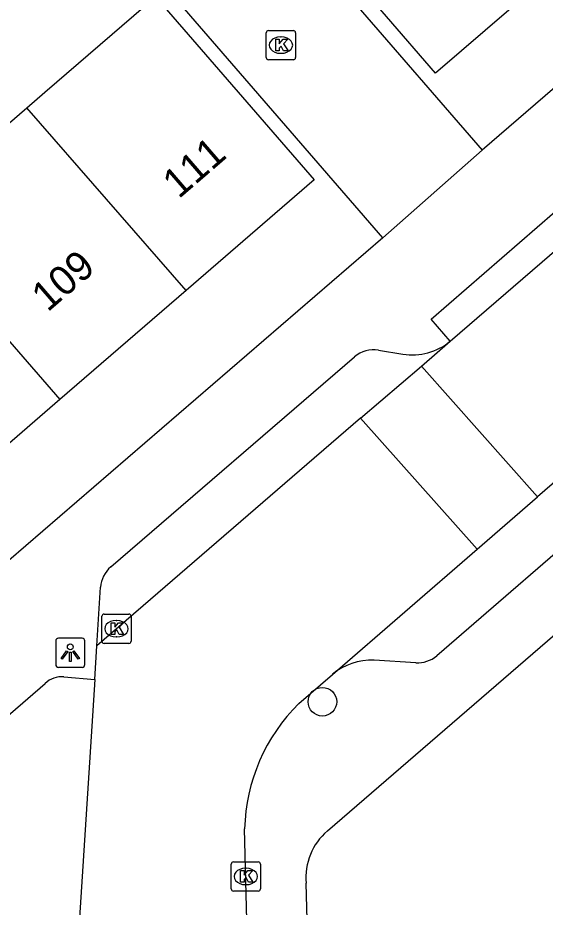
# Model space of a CAD drawing. Extents: x 160304 to 160954, y 383686 to 384161.
# Drawn here: x 160578.41 to 160596.44, y 384040.18 to 384070.59 of the extents above; entities that cross this region are included whole.
import ezdxf

# ---------------------------------------------------------------- set-up
doc = ezdxf.new("R2010")
doc.units = 0
for name, color, linetype in [('IMGEO_Boom', 7, 'Continuous'), ('IMGEO_Kolk', 7, 'Continuous'), ('IMGEO_Lichtpunt', 7, 'Continuous'), ('IMGEO_Pand', 7, 'Continuous'), ('IMGEO_Pand_nummerreeks', 7, 'Continuous'), ('IMGEO_Rijbaan_lokaal_open', 7, 'Continuous'), ('IMGEO_Voetpad_open', 7, 'Continuous')]:
    doc.layers.add(name, color=color, linetype=linetype)

msp = doc.modelspace()

# ---------------------------------------------------------------- linework, layer by layer
at = {"layer": 'IMGEO_Boom'}
msp.add_circle((160588.824, 384047.207), 0.489, dxfattribs=at)
at = {"layer": 'IMGEO_Kolk'}
for p, q in [((160586.905, 384069.225), (160586.905, 384070.077)), ((160586.98, 384070.151), (160587.832, 384070.151)), ((160587.393, 384069.931), (160587.418, 384069.931)), ((160587.906, 384070.077), (160587.906, 384069.225)), ((160587.416, 384069.371), (160587.391, 384069.371)), ((160587.832, 384069.151), (160586.98, 384069.151)), ((160581.357, 384050.203), (160582.209, 384050.203)), ((160581.282, 384049.277), (160581.282, 384050.129)), ((160581.77, 384049.983), (160581.795, 384049.983)), ((160582.283, 384050.129), (160582.283, 384049.277)), ((160581.793, 384049.423), (160581.768, 384049.423)), ((160582.209, 384049.203), (160581.357, 384049.203)), ((160585.705, 384040.809), (160585.705, 384041.661)), ((160585.78, 384041.735), (160586.632, 384041.735)), ((160586.706, 384041.661), (160586.706, 384040.809)), ((160586.193, 384041.515), (160586.218, 384041.515)), ((160586.632, 384040.735), (160585.78, 384040.735)), ((160586.216, 384040.955), (160586.191, 384040.955))]:
    msp.add_line(p, q, dxfattribs=at)
for points in [[(160586.905, 384069.225), (160586.905, 384070.077)], [(160586.98, 384070.151), (160587.832, 384070.151)], [(160587.906, 384070.077), (160587.906, 384069.225)], [(160587.226, 384069.851), (160587.349, 384069.851), (160587.349, 384069.7), (160587.479, 384069.851), (160587.643, 384069.851), (160587.497, 384069.7), (160587.65, 384069.451), (160587.498, 384069.451), (160587.413, 384069.615), (160587.349, 384069.548), (160587.349, 384069.451), (160587.226, 384069.451), (160587.226, 384069.851)], [(160587.832, 384069.151), (160586.98, 384069.151)], [(160581.357, 384050.203), (160582.209, 384050.203)], [(160581.282, 384049.277), (160581.282, 384050.129)], [(160581.603, 384049.903), (160581.726, 384049.903), (160581.726, 384049.752), (160581.856, 384049.903), (160582.02, 384049.903), (160581.874, 384049.752), (160582.027, 384049.503), (160581.875, 384049.503), (160581.79, 384049.667), (160581.726, 384049.6), (160581.726, 384049.503), (160581.603, 384049.503), (160581.603, 384049.903)], [(160582.283, 384050.129), (160582.283, 384049.277)], [(160582.209, 384049.203), (160581.357, 384049.203)], [(160585.705, 384040.809), (160585.705, 384041.661)], [(160585.78, 384041.735), (160586.632, 384041.735)], [(160586.706, 384041.661), (160586.706, 384040.809)], [(160586.026, 384041.435), (160586.149, 384041.435), (160586.149, 384041.284), (160586.279, 384041.435), (160586.443, 384041.435), (160586.297, 384041.284), (160586.45, 384041.035), (160586.298, 384041.035), (160586.213, 384041.199), (160586.149, 384041.132), (160586.149, 384041.035), (160586.026, 384041.035), (160586.026, 384041.435)], [(160586.632, 384040.735), (160585.78, 384040.735)]]:
    msp.add_lwpolyline(points, dxfattribs=at)
for centre, start, end in [((160586.982, 384070.075), 91.552, 178.448), ((160586.982, 384070.075), 91.552, 178.448), ((160587.83, 384070.075), 1.552, 88.448), ((160587.83, 384070.075), 1.552, 88.448), ((160586.982, 384069.227), 181.552, 268.448), ((160586.982, 384069.227), 181.552, 268.448), ((160587.83, 384069.227), 271.552, 358.448), ((160587.83, 384069.227), 271.552, 358.448), ((160581.359, 384050.127), 91.552, 178.448), ((160581.359, 384050.127), 91.552, 178.448), ((160582.207, 384050.127), 1.552, 88.448), ((160582.207, 384050.127), 1.552, 88.448), ((160581.359, 384049.279), 181.552, 268.448), ((160581.359, 384049.279), 181.552, 268.448), ((160582.207, 384049.279), 271.552, 358.448), ((160582.207, 384049.279), 271.552, 358.448), ((160585.782, 384041.659), 91.552, 178.448), ((160585.782, 384041.659), 91.552, 178.448), ((160586.63, 384041.659), 1.552, 88.448), ((160586.63, 384041.659), 1.552, 88.448), ((160585.782, 384040.811), 181.552, 268.448), ((160585.782, 384040.811), 181.552, 268.448), ((160586.63, 384040.811), 271.552, 358.448), ((160586.63, 384040.811), 271.552, 358.448)]:
    msp.add_arc(centre, 0.0765, start, end, dxfattribs=at)
for centre, major_axis, ratio, start_param, end_param in [((160587.392, 384069.651), (-0.387, 0.002), 0.722429, 4.712389, 7.853982), ((160587.417, 384069.651), (-0.39, 0.002), 0.717154, 1.570796, 4.712389), ((160581.769, 384049.703), (-0.387, 0.002), 0.722429, 4.712389, 7.853982), ((160581.794, 384049.703), (-0.39, 0.002), 0.717154, 1.570796, 4.712389), ((160586.192, 384041.235), (-0.387, 0.002), 0.722429, 4.712389, 7.853982), ((160586.217, 384041.235), (-0.39, 0.002), 0.717154, 1.570796, 4.712389)]:
    msp.add_ellipse(centre, major_axis=major_axis, ratio=ratio, start_param=start_param, end_param=end_param, dxfattribs=at)
at = {"layer": 'IMGEO_Lichtpunt'}
for p, q in [((160579.705, 384049.285), (160579.705, 384048.478)), ((160579.705, 384049.285), (160579.705, 384048.478)), ((160580.607, 384049.38), (160579.799, 384049.38)), ((160580.607, 384049.38), (160579.799, 384049.38)), ((160580.701, 384048.478), (160580.701, 384049.285)), ((160580.701, 384048.478), (160580.701, 384049.285)), ((160579.799, 384048.384), (160580.607, 384048.384)), ((160579.799, 384048.384), (160580.607, 384048.384))]:
    msp.add_line(p, q, dxfattribs=at)
for points in [[(160580.079, 384048.949), (160580.118, 384048.921), (160579.93, 384048.659), (160579.892, 384048.686), (160580.079, 384048.949)], [(160580.291, 384048.921), (160580.329, 384048.948), (160580.516, 384048.686), (160580.477, 384048.658), (160580.291, 384048.921)], [(160580.181, 384048.901), (160580.228, 384048.901), (160580.228, 384048.579), (160580.181, 384048.579), (160580.181, 384048.901)]]:
    msp.add_lwpolyline(points, dxfattribs=at)
msp.add_circle((160580.204, 384049.083), 0.0994, dxfattribs=at)
for centre, start, end in [((160579.799, 384049.285), 90, 180), ((160579.799, 384049.285), 90, 180), ((160580.607, 384049.285), 0, 90), ((160580.607, 384049.285), 0, 90), ((160579.799, 384048.478), 180, 270), ((160579.799, 384048.478), 180, 270), ((160580.607, 384048.478), 270, 0), ((160580.607, 384048.478), 270, 360)]:
    msp.add_arc(centre, 0.0946, start, end, dxfattribs=at)
at = {"layer": 'IMGEO_Pand'}
for points in [[(160596.974, 384072.386), (160592.694, 384068.69), (160587.665, 384074.513), (160585.913, 384076.542), (160590.193, 384080.238), (160591.945, 384078.209)], [(160578.719, 384067.513), (160579.338, 384068.048), (160583.122, 384071.316), (160588.539, 384065.044), (160584.165, 384061.267)], [(160574.41, 384063.793), (160578.719, 384067.513)], [(160584.165, 384061.267), (160578.719, 384067.513)], [(160574.41, 384063.793), (160579.845, 384057.535)], [(160584.165, 384061.267), (160579.845, 384057.535)], [(160579.845, 384057.535), (160575.545, 384053.821)]]:
    msp.add_lwpolyline(points, dxfattribs=at)
at = {"layer": 'IMGEO_Rijbaan_lokaal_open'}
for points in [[(160578.615, 384084.142), (160585.508, 384076.191), (160594.287, 384066.063)], [(160590.891, 384063.065), (160578.802, 384077.039), (160575.999, 384077.117)], [(160611.687, 384067.609), (160596.18, 384054.208)], [(160594.287, 384066.063), (160590.891, 384063.065)], [(160593.19, 384059.531), (160597.248, 384063.027), (160597.427, 384063.191)], [(160592.207, 384058.683), (160593.19, 384059.531)], [(160590.131, 384056.895), (160592.207, 384058.683)], [(160596.18, 384054.208), (160592.207, 384058.683)], [(160590.131, 384056.895), (160581.111, 384049.123)], [(160594.111, 384052.42), (160590.131, 384056.895)], [(160594.111, 384052.42), (160596.18, 384054.208)], [(160589.163, 384048.144), (160594.111, 384052.42)], [(160581.037, 384047.97), (160581.111, 384049.123)], [(160588.016, 384047.153), (160589.163, 384048.144)], [(160581.037, 384047.97), (160580.353, 384037.334)], [(160586.437, 384032.15), (160586.162, 384042.862)]]:
    msp.add_lwpolyline(points, dxfattribs=at)
msp.add_arc((160592.455, 384042.689), 6.295, 134.8395, 178.4253, dxfattribs=at)
at = {"layer": 'IMGEO_Voetpad_open'}
for points in [[(160630.096, 384096.946), (160594.287, 384066.063)], [(160588.993, 384042.795), (160607.555, 384058.819), (160616.616, 384066.641), (160617.548, 384067.446)], [(160610.683, 384064.29), (160592.733, 384048.779)], [(160593.19, 384059.531), (160592.537, 384060.288), (160596.775, 384063.949), (160597.427, 384063.191)], [(160590.891, 384063.065), (160577.514, 384051.539), (160577.428, 384049.127), (160562.223, 384035.951)], [(160581.585, 384051.814), (160589.923, 384058.999)], [(160590.739, 384059.228), (160591.577, 384059.089)], [(160581.111, 384049.123), (160581.24, 384051.121)], [(160592.018, 384048.537), (160590.591, 384048.625)], [(160579.979, 384048.063), (160581.037, 384047.97)], [(160576.201, 384045.119), (160579.344, 384047.835)], [(160588.54, 384030.95), (160588.268, 384041.002)]]:
    msp.add_lwpolyline(points, dxfattribs=at)
for centre, radius, start, end in [((160591.904, 384061.059), 1.997, 260.5677, 310.0807), ((160590.577, 384058.238), 1.003, 80.6908, 130.6614), ((160582.242, 384051.055), 1.004, 130.8634, 176.2051), ((160590.513, 384046.497), 2.13, 87.8977, 129.3329), ((160592.078, 384049.537), 1.001, 266.5598, 310.8381), ((160579.936, 384047.186), 0.879, 87.17, 132.3318), ((160590.352, 384041.202), 2.094, 130.4793, 185.4888)]:
    msp.add_arc(centre, radius, start, end, dxfattribs=at)

# ---------------------------------------------------------------- texts
at = {"layer": 'IMGEO_Pand_nummerreeks'}
for s, p in [('111', (160583.91, 384064.376)), ('109', (160579.429, 384060.506))]:
    msp.add_text(s, height=1, rotation=40.8144, dxfattribs=at).set_placement(p)

doc.saveas('drawing.dxf')
